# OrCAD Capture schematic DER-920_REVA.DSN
size Custom; title: DER 920; rev: A
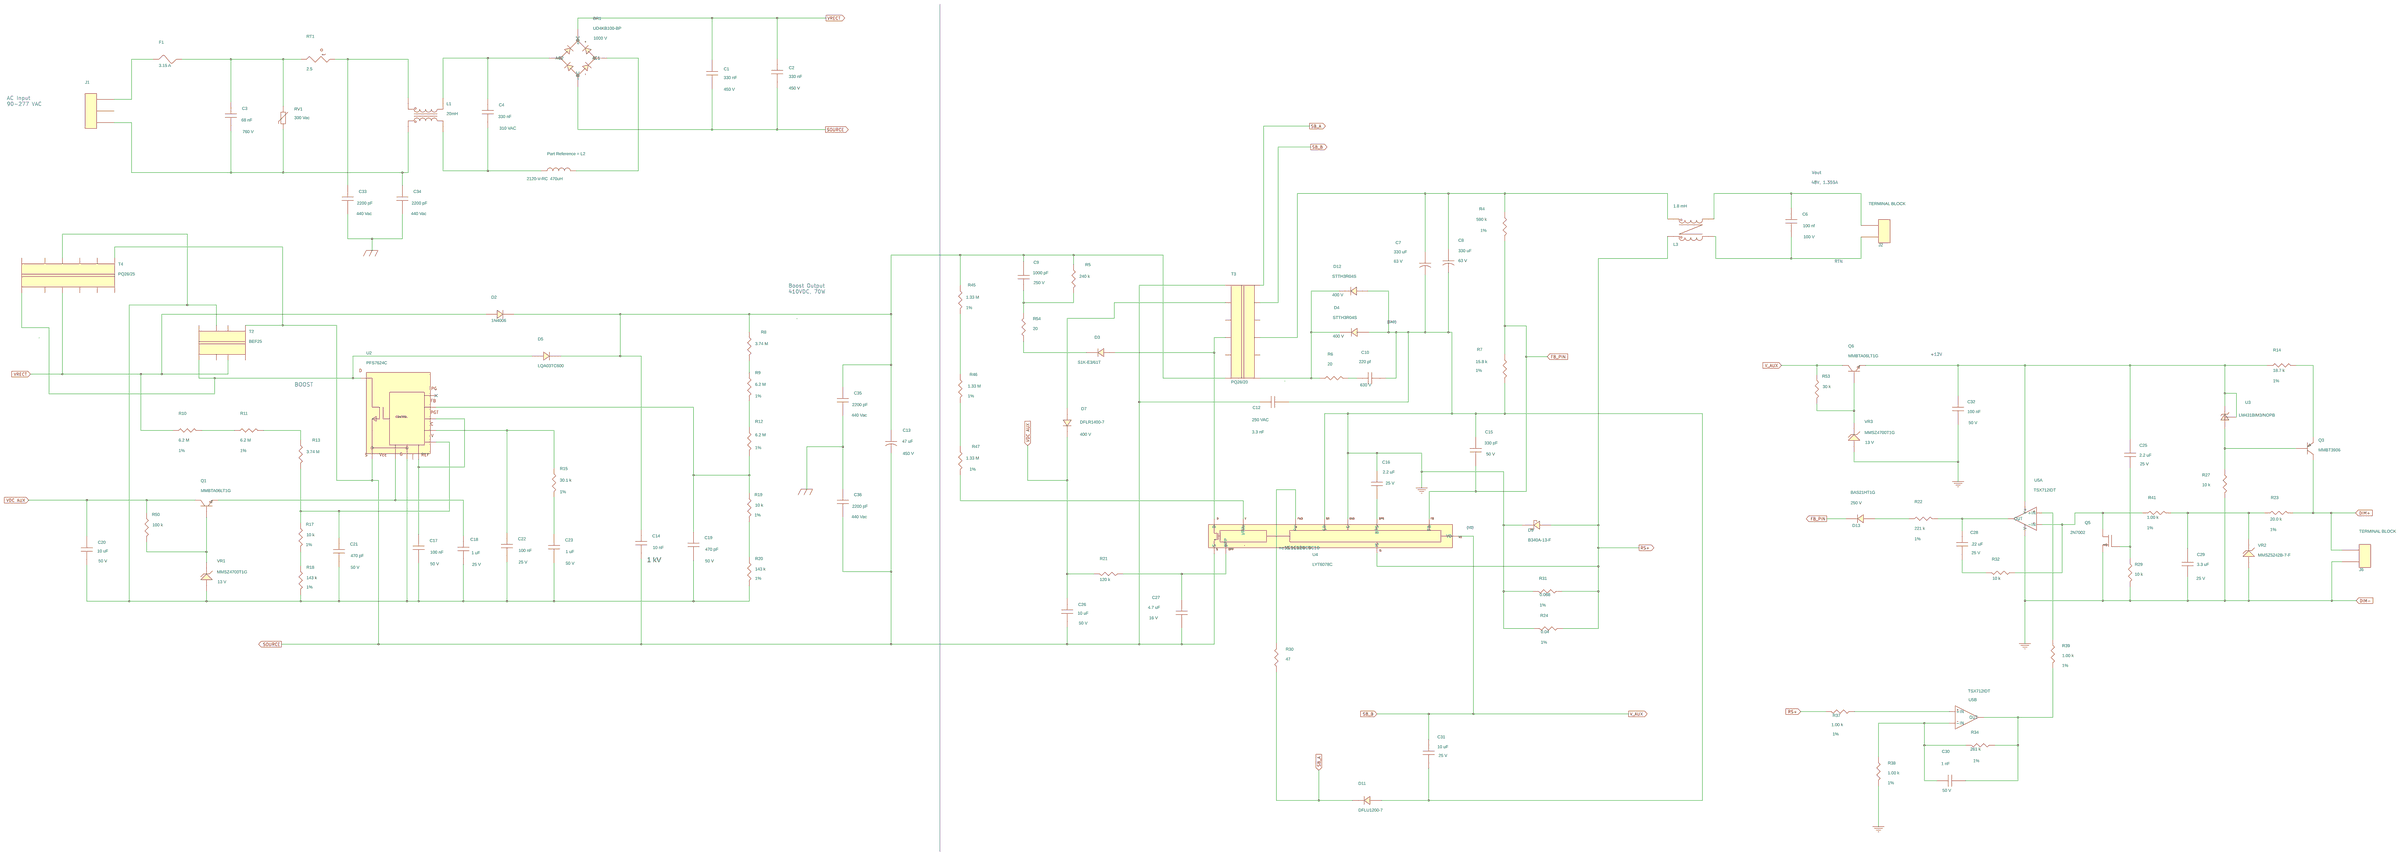
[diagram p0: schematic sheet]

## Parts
BR1  UD4KB100-BP  [pidaxbridgeD3K]
C1  330 nF  [pi_np_caprad512x299ls394d040]
C2  330 nF  [pi_np_caprad512x299ls394d040]
C3  68 nF  [piNPcapRAD18x6xLS15mmd040]
C4  330 nF  [pinpxcaprad710x315590046]
C6  100 nf  [pismc0805]
C7  330 uF  [pipolcapcyld400ls200040]
C8  330 uF  [pipolcapcyld400ls200040]
C9  1000 pF  [pismc0805]
C10  220 pf  [pismc1206]
C12  3.3 nF  [pinpycaprad540x290ls400040]
C13  47 uF  [pipolcapclyd600ls300040]
C14  10 nF  [pi_np_cap250x200ls170d030]
C15  330 pF  [pismc0603]
C16  2.2 uF  [pismc1206]
C17  100 nF  [pismc0805]
C18  1 uF  [pismc0805]
C19  470 pF  [pismc0805]
C20  10 uF  [pismc1206]
C21  470 pF  [pismc0805]
C22  100 nF  [pismc0805]
C23  1 uF  [pismc0805]
C25  2.2 uF  [pismc0805]
C26  10 uF  [pismc1206]
C27  4.7 uF  [pismc0805]
C28  .22 uF  [pismc1206]
C29  3.3 uF  [pismc0805]
C30  1 nF  [pismc0805]
C31  10 uF  [pismc1206]
C32  100 nF  [pismc0805]
C33  2200 pF  [pinpcapraD9mmxLS10mm030]
C34  2200 pF  [pinpcapraD9mmxLS10mm030]
C35  2200 pF  [pinpcapraD9mmxLS10mm030]
C36  2200 pF  [pinpcapraD9mmxLS10mm030]
D2  1N4006  [pidv200x110x040do41]
D3  S1K-E3/61T  [pismdo214ac12]
D4  STTH3R04S  [pismdo214ab12]
D5  LQA03TC600  [pidvt0220acreva]
D7  DFLR1400-7  [pismddflr120012]
D9  B340A-13-F  [pismdo214ac12]
D11  DFLU1200-7  [pismddflr120012]
D12  STTH3R04S  [pismdo214ab12]
D13  BAS21HT1G  [pismsod323]
F1  3.15 A  [pi_rst_microfuse]
J1  TERMINAL BLOCK  [pi_term_block_3pin]
J2  TERMINAL BLOCK  [pi_term_block_2pin_ls200]
J6  TERMINAL BLOCK  [pi_term_block_2pin_ls200]
L1  20mH  [pi_ind_4p_690x512ls300x200d055]
L2  2120-V-RC  470uH  [pi_toroid_2p_350x860_ls330_d038]
L3  1.8 mH  [pi_coil_16x8_LS8x7p5]
Q1  MMBTA06LT1G  [pismsot23123_1]
Q3  MMBT3906  [pismsot23123_1]
Q5  2N7002  [pismsot23123_1]
Q6  MMBTA06LT1G  [pismsot23123_1]
R4  590 k  [pismr0805]
R5  240 k  [pismr1206]
R6  20  [pismr1206]
R7  15.8 k  [pismr0805]
R8  3.74 M  [pismr1206]
R9  6.2 M  [pismr1206]
R10  6.2 M  [pismr1206]
R11  6.2 M  [pismr1206]
R12  6.2 M  [pismr1206]
R13  3.74 M  [pismr1206]
R14  18.7 k  [pismr0805]
R15  30.1 k  [pismr0805]
R17  10 k  [pismr0805]
R18  143 k  [pismr0805]
R19  10 k  [pismr0805]
R20  143 k  [pismr0805]
R21  120 k  [pismr1206]
R22  221 k  [pismr0805]
R23  20.0 k  [pismr1206]
R24  0.04  [pismr1206]
R27  10 k  [pismr0805]
R29  10 k  [pismr0805]
R30  47  [pismr1206]
R31  0.068  [pismr1206]
R32  10 k  [pismr0805]
R34  261 k  [pismr0805]
R37  1.00 k  [pismr0805]
R38  1.00 k  [pismr0805]
R39  1.00 k  [pismr0805]
R41  1.00 k  [pismr0805]
R45  1.33 M  [pismr1206]
R46  1.33 M  [pismr1206]
R47  1.33 M  [pismr1206]
R50  100 k  [pismr0805]
R53  30 k  [pismr0805]
R54  20  [pismr1206]
RT1  2.5  [pi_rad150x300ls200d030]
RV1  300 Vac  [pidisc350x225ls240x140040]
T2  BEF25  [pi_bobbin_ef25_8p_h]
T3  PQ26/20  [pi_bobbin_bpq26_20_12p]
T4  PQ26/25  [pibobbinpq262512p]
U2  PFS7624C  [PI_IC_INSOP24B]
U3  LM431BIM3/NOPB  [pismsot23123]
U4  LYT6078C  [pi_ic_insop_24d]
U5  TSX712IDT  [pismso8]  (sections A,B)
VR1  MMSZ4700T1G  [pi_sm_sod-123_12]
VR2  MMSZ5242B-7-F  [pi_sm_sod-123_12]
VR3  MMSZ4700T1G  [pi_sm_sod-123_12]

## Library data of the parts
BR1 = DISCRETE_BRIDGE_+~~-: ALT_SYMBOLS: pidaxbridgeD3K_horz; Disp_Voltage: 1000 V; FPLIST: pidaxbridgeD3K,pidaxbridgeD3K_horz; Part Number: 15-01213-00
C1 C2 = CAP_NP: ALT_SYMBOLS: pi_np_caprad512x299ls394d040_h; Disp_Voltage: 450 V; FPLIST: pi_np_caprad512x299ls394d040,pi_np_caprad512x299ls394d040_h; Part Number: 20-00973-00; Voltage: 450 V
C3 = CAP_NP: ALT_SYMBOLS: piNPcapRAD18x6xLS15mmd040H; Disp_Voltage: 760 V; FPLIST: piNPcapRAD18x6xLS15mmd040,piNPcapRAD18x6xLS15mmd040H; Part Number: 20-09050-00; Voltage: 760 V
C4 = CAP_NP: Disp_Voltage: 310 VAC; Part Number: 20-08604-00; Voltage: 310 VAC
C6 = CAP_NP: Disp_Voltage: 100 V; Part Number: 24-00026-00; Voltage: 100 V
C7 C8 = CAP_POL: ALT_SYMBOLS: pipolcapcyld400ls200040800h; COMPGROUP: 3; Disp_Voltage: 63 V; FPLIST: pipolcapcyld400ls200040,pipolcapcyld400ls200040800h; Part Number: 20-01117-00; Voltage: 63 V
C9 = CAP_NP: Disp_Voltage: 250 V; Part Number: 20-01451-00; Voltage: 250 V
C10 = CAP_NP: Disp_Voltage: 630 V; PCB Editor PCBFP: pismc0603; Part Number: 20-01036-00; Voltage: 630 V
C12 = CAP_NP: ALT_SYMBOLS: pinpycaprad540x290ls400040h; COMPGROUP: 3; Disp_Voltage: 250 VAC; FPLIST: pinpycaprad540x290ls400040,pinpycaprad540x290ls400040h; Part Number: 20-00377-00; Voltage: 250 VAC
C13 = CAP_POL: ALT_SYMBOLS: pipolcapd630ls3000401120lhoriz; Disp_Voltage: 450 V; FPLIST: pipolcapclyd600ls300040,pipolcapd630ls3000401120lhoriz; Part Number: 20-00519-00; Voltage: 450 V
C14 = CAP_NP: Disp_Voltage: 1 kV; Part Number: 20-00894-00; Voltage: 1 kV
C15 = CAP_NP: Disp_Voltage: 50 V; Part Number: 20-08676-00; Voltage: 50 V
C16 = CAP_NP: Disp_Voltage: 25 V; Part Number: 20-01034-00; Voltage: 25 V
C17 C32 = CAP_NP: Disp_Voltage: 50 V; Part Number: 20-00904-00; Voltage: 50 V
C18 = CAP_NP: Disp_Voltage: 25 V; Part Number: 20-09171-00; Voltage: 25 V
C19 C21 = CAP_NP: Disp_Voltage: 50 V; Part Number: 20-00205-00; Voltage: 50 V
C20 C26 = CAP_NP: ALT_SYMBOLS: pismc1206_1; Disp_Voltage: 50 V; FPLIST: pismc1206,pismc1206_1; Part Number: 20-08995-00; Voltage: 50 V
C22 = CAP_NP: Disp_Voltage: 25 V; Part Number: 20-08599-00; Voltage: 25 V
C23 = CAP_NP: Disp_Voltage: 50 V; Part Number: 20-09156-00; Voltage: 50 V
C25 = CAP_NP: Disp_Voltage: 25 V; Part Number: 20-08603-00; Voltage: 25 V
C27 = CAP_NP: Disp_Voltage: 16 V; Part Number: 20-09166-00; Voltage: 16 V
C28 = CAP_NP: Disp_Voltage: 25 V; Part Number: 20-01452-00; Voltage: 25 V
C29 = CAP_NP: Disp_Voltage: 25 V; Part Number: 20-01041-00; Voltage: 25 V
C30 = CAP_NP: Disp_Voltage: 50 V; Part Number: 20-08750-00; Voltage: 50 V
C31 = CAP_NP: Disp_Voltage: 25 V; Part Number: 20-08608-00; Voltage: 25 V
C33-C36 = CAP_NP: Disp_Voltage: 440 Vac; Part Number: 20-01453-00; Voltage: 440 Vac
D2 = DIODE: ALT_SYMBOLS: pidax475x125040do41,pidv200x110x040do41wbead,pidax390x125040do41; FPLIST: pidv200x110x040do41,pidax475x125040do41,pidv200x110x040do41wbead,pidax390x125040do41; Part Number: 15-00629-00
D3 = DIODE: Part Number: 15-01053-00
D4 D12 = DIODE: Disp_Voltage: 400 V; Part Number: 15-01274-00
D5 = DIODE: Part Number: 15-00834-00
D7 = DIODE: COMPGROUP: 1; Disp_Voltage: 400 V; Part Number: 15-01310-00
D9 = DIODE_SCHOTTKY: Part Number: 15-01172-00
D11 = DIODE: Part Number: 15-01043-00
D13 = DIODE: ALT_SYMBOLS: pismsod323_1; Disp_Voltage: 250 V; FPLIST: pismsod323,pismsod323_1; Part Number: 15-01247-00
F1 = FUSE: ALT_SYMBOLS: pirstmicrofusehoz; FPLIST: pi_rst_microfuse,pirstmicrofusehoz; Part Number: 40-00020-00
J1 = CON3: Part Number: 35-00175-00
J2 J6 = CON2: Part Number: 35-00277-00
L1 = INDUCTOR_4P_revD: ALT_SYMBOLS: pi_4p_700x400d055_horiz; FPLIST: pi_ind_4p_690x512ls300x200d055,pi_4p_700x400d055_horiz; Part Number: 30-04099-00
L2 = INDUCTOR: ALT_SYMBOLS: pi_2p_700x400d055_horiz; FPLIST: pi_toroid_2p_350x860_ls330_d038,pi_2p_700x400d055_horiz; Part Number: 32-00224-00
L3 = TORRID_4P_14_23: Part Number: 32-00375-00
Q1 Q6 = NPN_BEC: Part Number: 55-00072-00
Q3 = PNP_BEC: Part Number: 55-00049-00
Q5 = FET_N_GSD: Part Number: 50-00103-00
R4 = R: Disp_Tol: 1%; Part Number: 05-00854-00
R5 = R: Part Number: 05-01409-00
R6 R54 = R: Part Number: 05-01311-00
R7 = R: Disp_Tol: 1%; Part Number: 05-00703-00
R8 R13 = R: Part Number: 05-05572-00
R9-R12 = R: Disp_Tol: 1%; Part Number: 05-05567-00
R14 = R: Disp_Tol: 1%; Part Number: 05-00710-00
R15 = R: Disp_Tol: 1%; Part Number: 05-00730-00
R17 R19 = R: Disp_Tol: 1%; Part Number: 05-00684-00
R18 R20 = R: Disp_Tol: 1%; Part Number: 05-00795-00
R21 = R: Part Number: 05-01402-00
R22 = R: Disp_Tol: 1%; Part Number: 05-00813-00
R23 = R: Disp_Tol: 1%; Part Number: 05-00318-00
R24 = R: Disp_Tol: 1%; Part Number: 05-06446-00
R27 R29 R32 = R: Part Number: 05-01543-00
R30 = R: Part Number: 05-01320-00
R31 = R: Disp_Tol: 1%; Part Number: 05-06499-00
R34 = R: ALT_SYMBOLS: pismr0805_1; Disp_Tol: 1%; FPLIST: pismr0805,pismr0805_1; Part Number: 05-00820-00
R37-R39 R41 = R: Disp_Tol: 1%; Part Number: 05-03310-00
R45-R47 = R: Disp_Tol: 1%; Part Number: 05-05444-00
R50 = R: Part Number: 05-01567-00
R53 = R: Part Number: 05-01554-00
RT1 = THERMISTOR: ALT_SYMBOLS: pirad400x300ls200040_h; FPLIST: pi_rad150x300ls200d030,pirad400x300ls200040_h; Part Number: 90-00040-00
RV1 = VARISTOR: Part Number: 85-00031-00
T2 = BEF25_8P_GENERIC: Part Number: 25-00820-00
T3 = BPQ26_20_12P_GENERIC: Part Number: 25-00025-00
T4 = BPQ26_25_12P_GENERIC: Part Number: 25-00055-00
U2 = HIPERPFS-4-inSOP24B: Part Number: 10-01067-00
U3 = TL431_SOT-23_CAR: Part Number: 45-00232-00
U4 = LYT6: Part Number: 10-01226-00
U5 = TSX712IDT: Part Number: 45-00514-00
VR1 VR3 = DIODE_ZENER: Disp_Voltage: 13 V; Part Number: 15-01046-00
VR2 = DIODE_ZENER: Part Number: 15-01090-00

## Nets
GND: C7.2 C8.2 C10.2 C12.2 C15.1 C16.1 C29.1 C31.2 C32.2 D4.2 D9.1 D11.2 D12.2 J6.1 Q5.2(S) R7.2 R24.2 R27.2 R29.2 R31.2 R38.2 U4.2(G) U4.5(SR) U5.4(V-) VR2.2 VR3.2
GND_EARTH: C33.2 C34.2 C35.2 C36.1
DIM+: J6.2 Q3.3(COLLECTOR) R23.2
FB_PIN: C15.2 D13.1 R4.2 R7.1 U4.3(FB)
NC8: U4.8(NC8)
NC9: U4.9(NC9)
NC10: U4.10(NC10)
NC11: U4.11(NC11)
NC12: U4.12(NC12)
NC15: U4.15(nc15)
RS+: D9.2 L3.2 R24.1 R31.1 R37.2 U4.1(IS)
SB_A: D11.1 R30.1 T3.7
SB_B: C31.1 Q6.3(COLLECTOR) R53.1 T3.8 U4.6(VO)
SOURCE: BR1.4(-DC) C1.2 C2.2 C12.1 C13.2 C14.2 C26.2 C27.2 C36.2 T2.5 T3.6 T4.7 U2.24(S) U4.16(S)
VDC AUX: C20.1 C26.1 D7.1 Q1.3(COLLECTOR) R21.1 R50.1
VRECT: BR1.1(+DC) C1.1 C2.1 D2.2 R10.1 T2.3 T4.3
N11474046: F1.1 J1.3
N11474062: C3.1 F1.2 RT1.1 RV1.1
N11474110: C33.1 L1.4 RT1.2
N11474114: BR1.3(AC2) C4.1 L1.3
N11474138: BR1.2(AC1) L2.2
N11474236: C3.2 C34.1 J1.1 L1.1 RV1.2
N11474420: C4.2 L1.2 L2.1
N11475153: C9.2 C13.1 C14.1 C35.1 D2.1 D5.1 R5.1 R8.1 R45.1 T3.1
N11476179: D5.2 T2.1 T4.1 U2.16(D)
N11479125: C18.1 Q1.2(EMITTER) U2.1(VCC)
N11479237: C17.2 C18.2 C19.2 C20.2 C21.2 C22.2 C23.2 R18.2 R20.2 T2.7 T4.10 U2.2(G) VR1.2
N11479555: C22.1 R15.1 U2.5(C)
N11479611: C23.1 R15.2
N11480864: R10.2 R11.1
N11480868: R11.2 R13.1
N11480902: C21.1 R13.2 R17.1 U2.4(V)
N11482311: R8.2 R9.1
N11482333: R9.2 R12.2
N11482355: C19.1 R12.1 R19.1 U2.6(FB)
N11498787: C7.1 C8.1 L3.1 R4.1 T3.10
N11498823: C6.1 J2.2 L3.4
N11498915: C6.2 J2.1 L3.3
N11498945: C9.1 R5.2 R54.2
N11499167: D4.1 D12.1 R6.2 T3.12
N11499175: C10.1 R6.1
N11499225: D3.2 T3.3 U4.24(D)
N11499609: R30.2 U4.7(FW)
N11499647: R47.2 U4.13(VPIN)
N11499655: C16.2 U4.4(BPS)
N11499799: C27.1 R21.2 U4.14(BPP)
N11939314: R19.2 R20.1
N11966145: D7.2 T3.5
N11977822: C17.1 U2.3(REF) U2.8(PGT)
N11995900: Q1.1(BASE) R50.2 VR1.1
N12000412: R17.2 R18.1
N12016680: R45.2 R46.1
N12017060: R46.2 R47.1
N12033400: C25.2 C32.1 Q6.2(EMITTER) R14.1 U3.1(C) U3.3(VREF) U5.8(V+)
N12033444: Q3.2(EMITTER) R14.2
N12033508: Q3.1(BASE) R27.1 U3.2(A)
N12033698: R39.1 U5.3(+IN)
N12033710: C29.2 R23.1 R41.2 VR2.1
N12033758: D13.2 R22.1
N12033762: C28.1 R22.2 U5.1(OUT)
N12033774: Q5.3(D) R32.1 R41.1 U5.2(-IN)
N12033856: C25.1 Q5.1(G) R29.1
N12033928: C28.2 R32.2
N12034090: C30.1 R34.2 R38.1 U5.6(-IN)
N12034098: C30.2 R34.1 R39.2 U5.7(OUT)
N12052159: Q6.1(BASE) R53.2 VR3.1
N12053445: D3.1 R54.1
N12080403: R37.1 U5.5(+IN)

Not connected (* = marked no-connect by the designer): J1 2; T2 2 4 6 8; T3 2 4 9 11; T4 2 4 5 6 8 9 11 12; U2 7(PG)* 12(G12)

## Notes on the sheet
- AC Input
  90-277 VAC
- Vout
- 48V, 1.355A
- RTN
- Boost Output
  410VDC, 70W
- (GND)
- +12V
- BOOST
- (VO)
